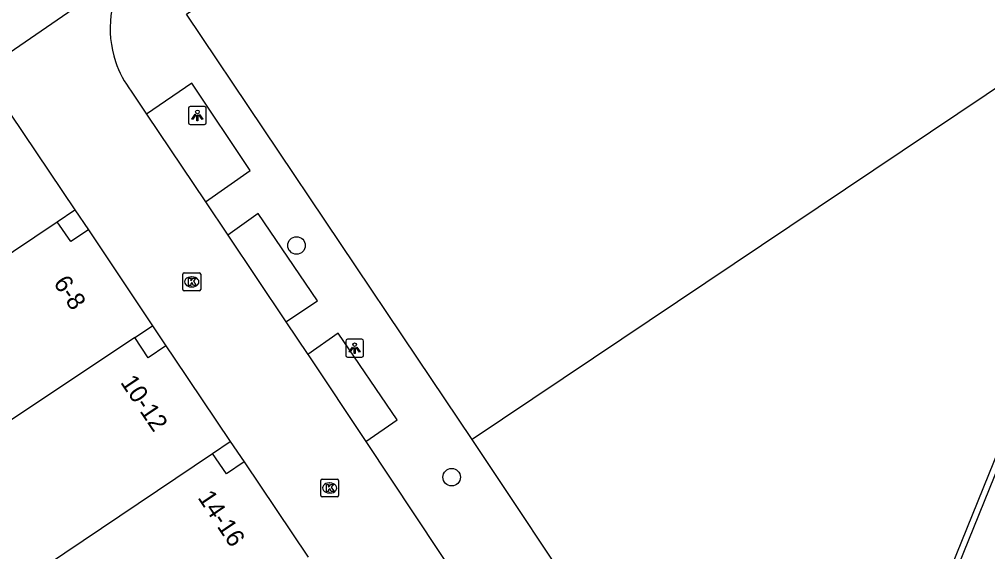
# Model space of a CAD drawing. Extents: x 161087 to 161922, y 382574 to 383873.
# Drawn here: x 161682.4 to 161736.5, y 382989.2 to 383018.9 of the extents above; entities that cross this region are included whole.
import ezdxf

# ---------------------------------------------------------------- set-up
doc = ezdxf.new("R2010")
doc.units = 0
for name, color, linetype in [('IMGEO_Boom', 7, 'Continuous'), ('IMGEO_Haag', 7, 'Continuous'), ('IMGEO_Kolk', 7, 'Continuous'), ('IMGEO_Lichtpunt', 7, 'Continuous'), ('IMGEO_Pand', 7, 'Continuous'), ('IMGEO_Pand_nummerreeks', 7, 'Continuous'), ('IMGEO_Rijbaan_lokaal_open', 7, 'Continuous'), ('IMGEO_Voetpad_open', 7, 'Continuous')]:
    doc.layers.add(name, color=color, linetype=linetype)

msp = doc.modelspace()

# ---------------------------------------------------------------- linework, layer by layer
at = {"layer": 'IMGEO_Boom'}
for centre in [(161697.852, 383006.295), (161706.519, 382993.343)]:
    msp.add_circle(centre, 0.489, dxfattribs=at)
at = {"layer": 'IMGEO_Haag'}
for points in [[(161747.272, 383020.049), (161741.948, 383006.903), (161730.157, 382977.79)], [(161730.52, 382977.756), (161742.9, 383008.325), (161745.252, 383014.216), (161747.477, 383019.703)]]:
    msp.add_lwpolyline(points, dxfattribs=at)
at = {"layer": 'IMGEO_Kolk'}
for p, q in [((161691.494, 383003.835), (161691.494, 383004.687)), ((161691.569, 383004.761), (161692.421, 383004.761)), ((161691.982, 383004.541), (161692.007, 383004.541)), ((161692.495, 383004.687), (161692.495, 383003.835)), ((161692.005, 383003.981), (161691.98, 383003.981)), ((161692.421, 383003.761), (161691.569, 383003.761)), ((161699.202, 382992.315), (161699.202, 382993.167)), ((161699.277, 382993.241), (161700.129, 382993.241)), ((161700.203, 382993.167), (161700.203, 382992.315)), ((161699.69, 382993.021), (161699.715, 382993.021)), ((161700.129, 382992.241), (161699.277, 382992.241)), ((161699.713, 382992.461), (161699.688, 382992.461))]:
    msp.add_line(p, q, dxfattribs=at)
for points in [[(161691.494, 383003.835), (161691.494, 383004.687)], [(161691.569, 383004.761), (161692.421, 383004.761)], [(161691.815, 383004.461), (161691.938, 383004.461), (161691.938, 383004.31), (161692.068, 383004.461), (161692.232, 383004.461), (161692.086, 383004.31), (161692.239, 383004.061), (161692.087, 383004.061), (161692.002, 383004.225), (161691.938, 383004.158), (161691.938, 383004.061), (161691.815, 383004.061), (161691.815, 383004.461)], [(161692.495, 383004.687), (161692.495, 383003.835)], [(161692.421, 383003.761), (161691.569, 383003.761)], [(161699.202, 382992.315), (161699.202, 382993.167)], [(161699.277, 382993.241), (161700.129, 382993.241)], [(161700.203, 382993.167), (161700.203, 382992.315)], [(161699.523, 382992.941), (161699.646, 382992.941), (161699.646, 382992.79), (161699.776, 382992.941), (161699.94, 382992.941), (161699.794, 382992.79), (161699.947, 382992.541), (161699.795, 382992.541), (161699.71, 382992.705), (161699.646, 382992.638), (161699.646, 382992.541), (161699.523, 382992.541), (161699.523, 382992.941)], [(161700.129, 382992.241), (161699.277, 382992.241)]]:
    msp.add_lwpolyline(points, dxfattribs=at)
for centre, start, end in [((161691.571, 383004.685), 91.552, 178.448), ((161691.571, 383004.685), 91.552, 178.448), ((161692.419, 383004.685), 1.552, 88.448), ((161692.419, 383004.685), 1.552, 88.448), ((161691.571, 383003.837), 181.552, 268.448), ((161691.571, 383003.837), 181.552, 268.448), ((161692.419, 383003.837), 271.552, 358.448), ((161692.419, 383003.837), 271.552, 358.448), ((161699.279, 382993.165), 91.552, 178.448), ((161699.279, 382993.165), 91.552, 178.448), ((161700.127, 382993.165), 1.552, 88.448), ((161700.127, 382993.165), 1.552, 88.448), ((161699.279, 382992.317), 181.552, 268.448), ((161699.279, 382992.317), 181.552, 268.448), ((161700.127, 382992.317), 271.552, 358.448), ((161700.127, 382992.317), 271.552, 358.448)]:
    msp.add_arc(centre, 0.0765, start, end, dxfattribs=at)
for centre, major_axis, ratio, start_param, end_param in [((161691.981, 383004.261), (-0.387, 0.002), 0.722429, 4.712389, 7.853982), ((161692.006, 383004.261), (-0.39, 0.002), 0.717154, 1.570796, 4.712389), ((161699.689, 382992.741), (-0.387, 0.002), 0.722429, 4.712389, 7.853982), ((161699.714, 382992.741), (-0.39, 0.002), 0.717154, 1.570796, 4.712389)]:
    msp.add_ellipse(centre, major_axis=major_axis, ratio=ratio, start_param=start_param, end_param=end_param, dxfattribs=at)
at = {"layer": 'IMGEO_Lichtpunt'}
for p, q in [((161691.813, 383013.96), (161691.813, 383013.153)), ((161691.813, 383013.96), (161691.813, 383013.153)), ((161692.715, 383014.055), (161691.907, 383014.055)), ((161692.715, 383014.055), (161691.907, 383014.055)), ((161692.809, 383013.153), (161692.809, 383013.96)), ((161692.809, 383013.153), (161692.809, 383013.96)), ((161691.907, 383013.059), (161692.715, 383013.059)), ((161691.907, 383013.059), (161692.715, 383013.059)), ((161700.598, 383000.955), (161700.598, 383000.148)), ((161700.598, 383000.955), (161700.598, 383000.148)), ((161701.5, 383001.05), (161700.692, 383001.05)), ((161701.5, 383001.05), (161700.692, 383001.05)), ((161701.594, 383000.148), (161701.594, 383000.955)), ((161701.594, 383000.148), (161701.594, 383000.955)), ((161700.692, 383000.054), (161701.5, 383000.054)), ((161700.692, 383000.054), (161701.5, 383000.054))]:
    msp.add_line(p, q, dxfattribs=at)
for points in [[(161692.187, 383013.624), (161692.226, 383013.596), (161692.038, 383013.334), (161692, 383013.361), (161692.187, 383013.624)], [(161692.399, 383013.596), (161692.437, 383013.623), (161692.624, 383013.361), (161692.585, 383013.333), (161692.399, 383013.596)], [(161692.289, 383013.576), (161692.336, 383013.576), (161692.336, 383013.254), (161692.289, 383013.254), (161692.289, 383013.576)], [(161700.972, 383000.619), (161701.011, 383000.591), (161700.823, 383000.329), (161700.785, 383000.356), (161700.972, 383000.619)], [(161701.184, 383000.591), (161701.222, 383000.618), (161701.409, 383000.356), (161701.37, 383000.328), (161701.184, 383000.591)], [(161701.074, 383000.571), (161701.121, 383000.571), (161701.121, 383000.249), (161701.074, 383000.249), (161701.074, 383000.571)]]:
    msp.add_lwpolyline(points, dxfattribs=at)
for centre in [(161692.312, 383013.758), (161701.097, 383000.753)]:
    msp.add_circle(centre, 0.0994, dxfattribs=at)
for centre, start, end in [((161691.907, 383013.96), 90, 180), ((161691.907, 383013.96), 90, 180), ((161692.715, 383013.96), 0, 90), ((161692.715, 383013.96), 0, 90), ((161691.907, 383013.153), 180, 270), ((161691.907, 383013.153), 180, 270), ((161692.715, 383013.153), 270, 0), ((161692.715, 383013.153), 270, 360), ((161700.692, 383000.955), 90, 180), ((161700.692, 383000.955), 90, 180), ((161701.5, 383000.955), 0, 90), ((161701.5, 383000.955), 0, 90), ((161700.692, 383000.148), 180, 270), ((161700.692, 383000.148), 180, 270), ((161701.5, 383000.148), 270, 0), ((161701.5, 383000.148), 270, 360)]:
    msp.add_arc(centre, 0.0946, start, end, dxfattribs=at)
at = {"layer": 'IMGEO_Pand'}
for points in [[(161707.658, 382995.446), (161704.603, 383000), (161691.701, 383019.23), (161705.312, 383028.34)], [(161746.435, 383021.464), (161736.382, 383014.719), (161714.445, 383000), (161707.658, 382995.446)], [(161681.875, 383013.627), (161685.461, 383008.279)], [(161684.473, 383007.616), (161685.461, 383008.279)], [(161670.999, 382998.574), (161684.473, 383007.616)], [(161686.22, 383007.17), (161685.231, 383006.507), (161684.473, 383007.616)], [(161686.22, 383007.17), (161689.804, 383001.812)], [(161688.822, 383001.157), (161689.804, 383001.812)], [(161688.822, 383001.157), (161675.318, 382992.15)], [(161690.556, 383000.677), (161689.569, 383000.014), (161688.822, 383001.157)], [(161690.556, 383000.677), (161691.011, 383000), (161694.146, 382995.332)], [(161693.158, 382994.668), (161694.146, 382995.332)], [(161679.704, 382985.626), (161693.158, 382994.668)], [(161694.925, 382994.203), (161693.936, 382993.541), (161693.158, 382994.668)], [(161694.925, 382994.203), (161698.499, 382988.867)]]:
    msp.add_lwpolyline(points, dxfattribs=at)
at = {"layer": 'IMGEO_Rijbaan_lokaal_open'}
for points in [[(161688.351, 383021.57), (161680.278, 383016.018)], [(161688.611, 383014.912), (161689.471, 383013.631)], [(161689.471, 383013.631), (161692.76, 383008.731)], [(161685.461, 383008.279), (161686.22, 383007.17)], [(161692.76, 383008.731), (161694.015, 383006.861)], [(161694.015, 383006.861), (161697.262, 383002.023)], [(161689.804, 383001.812), (161690.556, 383000.677)], [(161697.262, 383002.023), (161698.485, 383000.202)], [(161698.485, 383000.202), (161698.538, 383000.123), (161701.717, 382995.339)], [(161694.146, 382995.332), (161694.925, 382994.203)], [(161701.717, 382995.339), (161711.324, 382980.879), (161718.85, 382969.89)]]:
    msp.add_lwpolyline(points, dxfattribs=at)
for centre, radius, start, end in [((161693.271, 383018.427), 5.838, 147.4261, 198.4905), ((161693.263, 383018.428), 5.832, 198.5288, 217.0819)]:
    msp.add_arc(centre, radius, start, end, dxfattribs=at)
at = {"layer": 'IMGEO_Voetpad_open'}
for points in [[(161692.76, 383008.731), (161695.26, 383010.482), (161692.007, 383015.362), (161689.471, 383013.631)], [(161697.262, 383002.023), (161699.025, 383003.208), (161695.711, 383008.073), (161694.015, 383006.861)], [(161701.717, 382995.339), (161703.482, 382996.552), (161700.169, 383001.386), (161698.485, 383000.202)], [(161721.244, 382975.057), (161721.113, 382975.256), (161707.658, 382995.446)]]:
    msp.add_lwpolyline(points, dxfattribs=at)

# ---------------------------------------------------------------- texts
at = {"layer": 'IMGEO_Pand_nummerreeks'}
for s, rotation, p in [('6-8', 304.1595, (161684.235, 383004.191)), ('10-12', 303.9591, (161687.979, 382998.643)), ('14-16', 303.863, (161692.3, 382992.198))]:
    msp.add_text(s, height=1, rotation=rotation, dxfattribs=at).set_placement(p)

doc.saveas('drawing.dxf')
